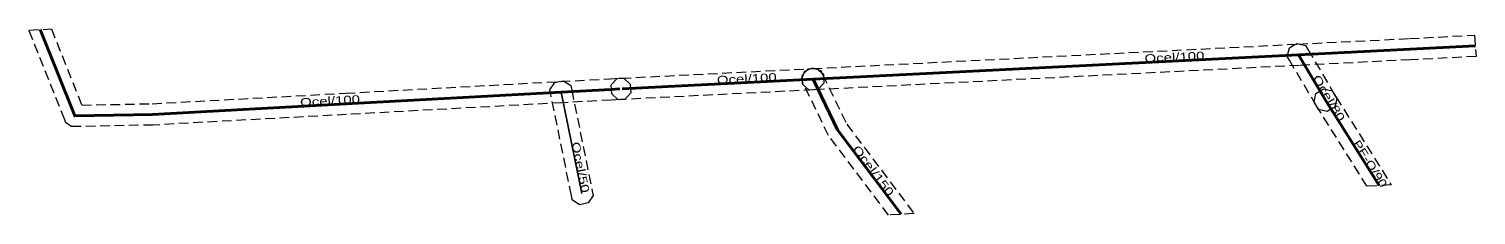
# Model space of a CAD drawing. Extents: x -466379 to -466244, y -1119127 to -1119110.
import ezdxf

# ---------------------------------------------------------------- set-up
doc = ezdxf.new("R2010")
doc.units = 0
doc.header["$LTSCALE"] = 0.3
doc.linetypes.add('MEDIUM_DASHED', pattern=[4.5, 3, -1.5])
doc.layers.add('1', color=7, linetype='MEDIUM_DASHED', lineweight=13)
doc.layers.add('14', color=7, linetype='Continuous', lineweight=40)
doc.layers.add('20', color=7, linetype='Continuous')

msp = doc.modelspace()

# ---------------------------------------------------------------- linework, layer by layer
at = {"layer": '1'}
for points in [[(-466376.114, -1119118.07), (-466379.472, -1119109.649), (-466377.363, -1119109.537), (-466374.512, -1119116.687), (-466367.917, -1119116.558), (-466349.798, -1119115.568), (-466329.625, -1119114.467), (-466324.983, -1119114.214), (-466324.128, -1119114.171), (-466323.715, -1119114.15), (-466323.1, -1119114.706), (-466323.079, -1119115.12), (-466323.058, -1119115.533), (-466323.614, -1119116.148), (-466324.028, -1119116.169), (-466324.879, -1119116.212), (-466329.517, -1119116.465), (-466349.689, -1119117.566), (-466367.843, -1119118.556), (-466375.165, -1119118.7), (-466375.478, -1119118.706), (-466375.998, -1119118.36)], [(-466243.945, -1119110.128), (-466243.811, -1119112.125), (-466249.95, -1119112.434), (-466260.392, -1119112.96), (-466305.918, -1119115.256), (-466306.331, -1119115.277), (-466306.946, -1119114.721), (-466306.967, -1119114.307), (-466306.988, -1119113.894), (-466306.432, -1119113.279), (-466306.018, -1119113.258), (-466260.492, -1119110.962), (-466250.05, -1119110.436)], [(-466259.791, -1119111.096), (-466259.581, -1119111.453), (-466257.069, -1119115.712), (-466256.859, -1119116.069), (-466257.065, -1119116.871), (-466257.422, -1119117.081), (-466257.779, -1119117.291), (-466258.581, -1119117.085), (-466258.791, -1119116.728), (-466261.303, -1119112.469), (-466261.513, -1119112.112), (-466261.307, -1119111.31), (-466260.95, -1119111.1), (-466260.593, -1119110.89)], [(-466305.504, -1119115.235), (-466305.918, -1119115.256), (-466323.813, -1119116.158), (-466324.226, -1119116.179), (-466324.841, -1119115.623), (-466324.862, -1119115.209), (-466324.883, -1119114.796), (-466324.327, -1119114.181), (-466323.913, -1119114.16), (-466306.018, -1119113.258), (-466305.605, -1119113.237), (-466304.99, -1119113.793), (-466304.969, -1119114.207), (-466304.948, -1119114.62)], [(-466302.803, -1119118.486), (-466296.496, -1119126.861), (-466298.89, -1119127.005), (-466304.517, -1119119.534), (-466306.868, -1119114.694), (-466307.049, -1119114.321), (-466306.777, -1119113.538), (-466306.405, -1119113.357), (-466306.032, -1119113.176), (-466305.249, -1119113.448), (-466305.068, -1119113.82)], [(-466328.673, -1119114.861), (-466328.591, -1119115.267), (-466326.657, -1119124.773), (-466326.575, -1119125.179), (-466327.032, -1119125.87), (-466327.438, -1119125.952), (-466327.844, -1119126.034), (-466328.535, -1119125.577), (-466328.617, -1119125.171), (-466330.551, -1119115.665), (-466330.633, -1119115.259), (-466330.176, -1119114.568), (-466329.77, -1119114.486), (-466329.364, -1119114.404)], [(-466251.76, -1119124.164), (-466254.035, -1119124.301), (-466258.615, -1119117.005), (-466258.772, -1119116.759), (-466258.995, -1119116.41), (-466258.818, -1119115.601), (-466258.469, -1119115.378), (-466258.12, -1119115.155), (-466257.311, -1119115.332), (-466257.088, -1119115.681), (-466256.925, -1119115.935)]]:
    msp.add_lwpolyline(points, close=True, dxfattribs=at)
at = {"layer": '14'}
for p, q in [((-466260.442, -1119111.961), (-466257.93, -1119116.22)), ((-466305.968, -1119114.257), (-466323.863, -1119115.159))]:
    msp.add_line(p, q, dxfattribs=at)
at = {"layer": '14', "lineweight": 25}
msp.add_line((-466329.571, -1119115.466), (-466327.637, -1119124.972), dxfattribs=at)
at = {"layer": '14'}
for points in [[(-466324.078, -1119115.17), (-466324.931, -1119115.213), (-466329.571, -1119115.466), (-466349.743, -1119116.567), (-466367.88, -1119117.557), (-466375.185, -1119117.7), (-466378.418, -1119109.593)], [(-466305.968, -1119114.257), (-466260.442, -1119111.961), (-466250, -1119111.435), (-466243.878, -1119111.126)], [(-466297.693, -1119126.933), (-466303.66, -1119119.01), (-466305.968, -1119114.257)], [(-466257.93, -1119116.22), (-466257.77, -1119116.47), (-466252.898, -1119124.232)]]:
    msp.add_lwpolyline(points, dxfattribs=at)

# ---------------------------------------------------------------- texts
at = {"layer": '20'}
for s, rotation, width, p in [('Ocel/100', 2.887, 1.4, (-466274.873, -1119112.689)), ('Ocel/100', 2.886, 1.4, (-466314.966, -1119114.71)), ('Ocel/80', 300.533, 1.4, (-466259.16, -1119114.133)), ('Ocel/100', 3.124, 1.4, (-466354.034, -1119116.801)), ('Ocel/50', 281.5, 1.4, (-466328.604, -1119120.219)), ('PE-O/90', 302.117, 1.3, (-466255.386, -1119120.268)), ('Ocel/150', 306.983, 1.4, (-466302.296, -1119120.821))]:
    msp.add_text(s, height=0.75, rotation=rotation, dxfattribs=dict(at, width=width)).set_placement(p)

doc.saveas('drawing.dxf')
